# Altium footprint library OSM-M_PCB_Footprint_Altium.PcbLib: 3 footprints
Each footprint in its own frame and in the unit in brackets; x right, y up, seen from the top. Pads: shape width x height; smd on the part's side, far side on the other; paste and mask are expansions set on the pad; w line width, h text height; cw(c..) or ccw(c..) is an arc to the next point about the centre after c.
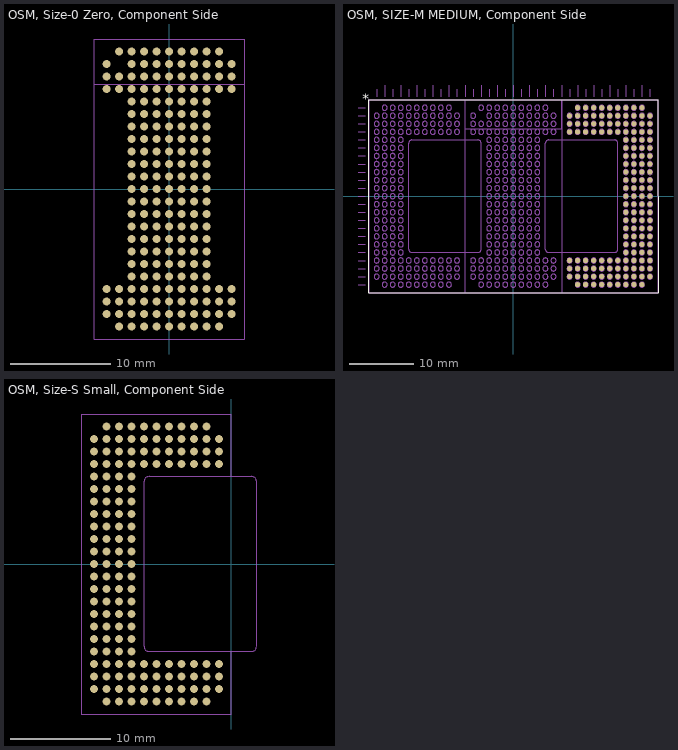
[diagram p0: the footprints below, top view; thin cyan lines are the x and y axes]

## OSM, Size-0 Zero, Component Side [mm] "OSM, Size-0 Zero"
height 3.8
pads (188):
  round 0.8 smd mask+0.051: A14(-5,13.75) A15(-3.75,13.75) A16(-2.5,13.75) A17(-1.25,13.75) A18(0,13.75) A19(1.25,13.75) A20(2.5,13.75) A21(3.75,13.75) A22(5,13.75) AA13(-6.25,-11.25) AA14(-5,-11.25) AA15(-3.75,-11.25) AA16(-2.5,-11.25) AA17(-1.25,-11.25) AA18(0,-11.25) AA19(1.25,-11.25) AA20(2.5,-11.25) AA21(3.75,-11.25) AA22(5,-11.25) AA23(6.25,-11.25) AB13(-6.25,-12.5) AB14(-5,-12.5) AB15(-3.75,-12.5) AB16(-2.5,-12.5) AB17(-1.25,-12.5) AB18(0,-12.5) AB19(1.25,-12.5) AB20(2.5,-12.5) AB21(3.75,-12.5) AB22(5,-12.5) AB23(6.25,-12.5) AC14(-5,-13.75) AC15(-3.75,-13.75) AC16(-2.5,-13.75) AC17(-1.25,-13.75) AC18(0,-13.75) AC19(1.25,-13.75) AC20(2.5,-13.75) AC21(3.75,-13.75) AC22(5,-13.75) B13(-6.25,12.5) B15(-3.75,12.5) B16(-2.5,12.5) B17(-1.25,12.5) B18(0,12.5) B19(1.25,12.5) B20(2.5,12.5) B21(3.75,12.5) B22(5,12.5) B23(6.25,12.5) C13(-6.25,11.25) C14(-5,11.25) C15(-3.75,11.25) C16(-2.5,11.25) C17(-1.25,11.25) C18(0,11.25) C19(1.25,11.25) C20(2.5,11.25) C21(3.75,11.25) C22(5,11.25) C23(6.25,11.25) D13(-6.25,10) D14(-5,10) D15(-3.75,10) D16(-2.5,10) D17(-1.25,10) D18(0,10) D19(1.25,10) D20(2.5,10) D21(3.75,10) D22(5,10) D23(6.25,10) E15(-3.75,8.75) E16(-2.5,8.75) E17(-1.25,8.75) E18(0,8.75) E19(1.25,8.75) E20(2.5,8.75) E21(3.75,8.75) F15(-3.75,7.5) F16(-2.5,7.5) F17(-1.25,7.5) F18(0,7.5) F19(1.25,7.5) F20(2.5,7.5) F21(3.75,7.5) G15(-3.75,6.25) G16(-2.5,6.25) G17(-1.25,6.25) G18(0,6.25) G19(1.25,6.25) G20(2.5,6.25) G21(3.75,6.25) H15(-3.75,5) H16(-2.5,5) H17(-1.25,5) H18(0,5) H19(1.25,5) H20(2.5,5) H21(3.75,5) J15(-3.75,3.75) J16(-2.5,3.75) J17(-1.25,3.75) J18(0,3.75) J19(1.25,3.75) J20(2.5,3.75) J21(3.75,3.75) K15(-3.75,2.5) K16(-2.5,2.5) K17(-1.25,2.5) K18(0,2.5) K19(1.25,2.5) K20(2.5,2.5) K21(3.75,2.5) L15(-3.75,1.25) L16(-2.5,1.25) L17(-1.25,1.25) L18(0,1.25) L19(1.25,1.25) L20(2.5,1.25) L21(3.75,1.25) M15(-3.75,0) M16(-2.5,0) M17(-1.25,0) M18(0,0) M19(1.25,0) M20(2.5,0) M21(3.75,0) N15(-3.75,-1.25) N16(-2.5,-1.25) N17(-1.25,-1.25) N18(0,-1.25) N19(1.25,-1.25) N20(2.5,-1.25) N21(3.75,-1.25) P15(-3.75,-2.5) P16(-2.5,-2.5) P17(-1.25,-2.5) P18(0,-2.5) P19(1.25,-2.5) P20(2.5,-2.5) P21(3.75,-2.5) R15(-3.75,-3.75) R16(-2.5,-3.75) R17(-1.25,-3.75) R18(0,-3.75) R19(1.25,-3.75) R20(2.5,-3.75) R21(3.75,-3.75) T15(-3.75,-5) T16(-2.5,-5) T17(-1.25,-5) T18(0,-5) T19(1.25,-5) T20(2.5,-5) T21(3.75,-5) U15(-3.75,-6.25) U16(-2.5,-6.25) U17(-1.25,-6.25) U18(0,-6.25) U19(1.25,-6.25) U20(2.5,-6.25) U21(3.75,-6.25) V15(-3.75,-7.5) V16(-2.5,-7.5) V17(-1.25,-7.5) V18(0,-7.5) V19(1.25,-7.5) V20(2.5,-7.5) V21(3.75,-7.5) W15(-3.75,-8.75) W16(-2.5,-8.75) W17(-1.25,-8.75) W18(0,-8.75) W19(1.25,-8.75) W20(2.5,-8.75) W21(3.75,-8.75) Y13(-6.25,-10) Y14(-5,-10) Y15(-3.75,-10) Y16(-2.5,-10) Y17(-1.25,-10) Y18(0,-10) Y19(1.25,-10) Y20(2.5,-10) Y21(3.75,-10) Y22(5,-10) Y23(6.25,-10)
Mechanical 13:
  lines w0.025: -7.508,15 -7.5,15 ; -7.5,15 7.5,15 7.5,-15 -7.5,-15 -7.5,15
  lines w0.051: -7.5,15 -7.5,10.5 7.5,10.5
  text "OSM, SIZE-0" at -4.122,12.686 h0.76
  text ".Designator" at -7.747,16.891 h1.52
3D body: height 0.05, standoff 0, extent -5.4,13.35 -4.6,14.15
3D body: height 0.05, standoff 0, extent -4.15,13.35 -3.35,14.15
3D body: height 0.05, standoff 0, extent -2.9,13.35 -2.1,14.15
3D body: height 0.05, standoff 0, extent -1.65,13.35 -0.85,14.15
3D body: height 0.05, standoff 0, extent -0.4,13.35 0.4,14.15
3D body: height 0.05, standoff 0, extent 0.85,13.35 1.65,14.15
3D body: height 0.05, standoff 0, extent 2.1,13.35 2.9,14.15
3D body: height 0.05, standoff 0, extent 3.35,13.35 4.15,14.15
3D body: height 0.05, standoff 0, extent 4.6,13.35 5.4,14.15
3D body: height 0.05, standoff 0, extent -6.65,12.1 -5.85,12.9
3D body: height 0.05, standoff 0, extent -4.15,12.1 -3.35,12.9
3D body: height 0.05, standoff 0, extent -2.9,12.1 -2.1,12.9
3D body: height 0.05, standoff 0, extent -1.65,12.1 -0.85,12.9
3D body: height 0.05, standoff 0, extent -0.4,12.1 0.4,12.9
3D body: height 0.05, standoff 0, extent 0.85,12.1 1.65,12.9
3D body: height 0.05, standoff 0, extent 2.1,12.1 2.9,12.9
3D body: height 0.05, standoff 0, extent 3.35,12.1 4.15,12.9
3D body: height 0.05, standoff 0, extent 4.6,12.1 5.4,12.9
3D body: height 0.05, standoff 0, extent -5.4,10.85 -4.6,11.65
3D body: height 0.05, standoff 0, extent -4.15,10.85 -3.35,11.65
3D body: height 0.05, standoff 0, extent -2.9,10.85 -2.1,11.65
3D body: height 0.05, standoff 0, extent -1.65,10.85 -0.85,11.65
3D body: height 0.05, standoff 0, extent -0.4,10.85 0.4,11.65
3D body: height 0.05, standoff 0, extent 0.85,10.85 1.65,11.65
3D body: height 0.05, standoff 0, extent 2.1,10.85 2.9,11.65
3D body: height 0.05, standoff 0, extent 3.35,10.85 4.15,11.65
3D body: height 0.05, standoff 0, extent 4.6,10.85 5.4,11.65
3D body: height 0.05, standoff 0, extent -5.4,9.6 -4.6,10.4
3D body: height 0.05, standoff 0, extent -4.15,9.6 -3.35,10.4
3D body: height 0.05, standoff 0, extent -2.9,9.6 -2.1,10.4
3D body: height 0.05, standoff 0, extent -1.65,9.6 -0.85,10.4
3D body: height 0.05, standoff 0, extent -0.4,9.6 0.4,10.4
3D body: height 0.05, standoff 0, extent 0.85,9.6 1.65,10.4
3D body: height 0.05, standoff 0, extent 2.1,9.6 2.9,10.4
3D body: height 0.05, standoff 0, extent 3.35,9.6 4.15,10.4
3D body: height 0.05, standoff 0, extent 4.6,9.6 5.4,10.4
3D body: height 0.05, standoff 0, extent -6.65,10.85 -5.85,11.65
3D body: height 0.05, standoff 0, extent -4.15,8.35 -3.35,9.15
3D body: height 0.05, standoff 0, extent -2.9,8.35 -2.1,9.15
3D body: height 0.05, standoff 0, extent -1.65,8.35 -0.85,9.15
3D body: height 0.05, standoff 0, extent -0.4,8.35 0.4,9.15
3D body: height 0.05, standoff 0, extent 0.85,8.35 1.65,9.15
3D body: height 0.05, standoff 0, extent 2.1,8.35 2.9,9.15
3D body: height 0.05, standoff 0, extent 3.35,8.35 4.15,9.15
3D body: height 0.05, standoff 0, extent 5.85,12.1 6.65,12.9
3D body: height 0.05, standoff 0, extent -4.15,7.1 -3.35,7.9
3D body: height 0.05, standoff 0, extent -2.9,7.1 -2.1,7.9
3D body: height 0.05, standoff 0, extent -1.65,7.1 -0.85,7.9
3D body: height 0.05, standoff 0, extent -0.4,7.1 0.4,7.9
3D body: height 0.05, standoff 0, extent 0.85,7.1 1.65,7.9
3D body: height 0.05, standoff 0, extent 2.1,7.1 2.9,7.9
3D body: height 0.05, standoff 0, extent 3.35,7.1 4.15,7.9
3D body: height 0.05, standoff 0, extent -4.15,5.85 -3.35,6.65
3D body: height 0.05, standoff 0, extent -2.9,5.85 -2.1,6.65
3D body: height 0.05, standoff 0, extent -1.65,5.85 -0.85,6.65
3D body: height 0.05, standoff 0, extent -0.4,5.85 0.4,6.65
3D body: height 0.05, standoff 0, extent 0.85,5.85 1.65,6.65
3D body: height 0.05, standoff 0, extent 2.1,5.85 2.9,6.65
3D body: height 0.05, standoff 0, extent 3.35,5.85 4.15,6.65
3D body: height 0.05, standoff 0, extent -4.15,4.6 -3.35,5.4
3D body: height 0.05, standoff 0, extent -2.9,4.6 -2.1,5.4
3D body: height 0.05, standoff 0, extent -1.65,4.6 -0.85,5.4
3D body: height 0.05, standoff 0, extent -0.4,4.6 0.4,5.4
3D body: height 0.05, standoff 0, extent 0.85,4.6 1.65,5.4
3D body: height 0.05, standoff 0, extent 2.1,4.6 2.9,5.4
3D body: height 0.05, standoff 0, extent 3.35,4.6 4.15,5.4
3D body: height 0.05, standoff 0, extent -4.15,3.35 -3.35,4.15
3D body: height 0.05, standoff 0, extent -2.9,3.35 -2.1,4.15
3D body: height 0.05, standoff 0, extent -1.65,3.35 -0.85,4.15
3D body: height 0.05, standoff 0, extent -0.4,3.35 0.4,4.15
3D body: height 0.05, standoff 0, extent 0.85,3.35 1.65,4.15
3D body: height 0.05, standoff 0, extent 2.1,3.35 2.9,4.15
3D body: height 0.05, standoff 0, extent 3.35,3.35 4.15,4.15
3D body: height 0.05, standoff 0, extent -4.15,2.1 -3.35,2.9
3D body: height 0.05, standoff 0, extent -2.9,2.1 -2.1,2.9
3D body: height 0.05, standoff 0, extent -1.65,2.1 -0.85,2.9
3D body: height 0.05, standoff 0, extent -0.4,2.1 0.4,2.9
3D body: height 0.05, standoff 0, extent 0.85,2.1 1.65,2.9
3D body: height 0.05, standoff 0, extent 2.1,2.1 2.9,2.9
3D body: height 0.05, standoff 0, extent 3.35,2.1 4.15,2.9
3D body: height 0.05, standoff 0, extent -4.15,0.85 -3.35,1.65
3D body: height 0.05, standoff 0, extent -2.9,0.85 -2.1,1.65
3D body: height 0.05, standoff 0, extent -1.65,0.85 -0.85,1.65
3D body: height 0.05, standoff 0, extent -0.4,0.85 0.4,1.65
3D body: height 0.05, standoff 0, extent 0.85,0.85 1.65,1.65
3D body: height 0.05, standoff 0, extent 2.1,0.85 2.9,1.65
3D body: height 0.05, standoff 0, extent 3.35,0.85 4.15,1.65
3D body: height 0.05, standoff 0, extent -4.15,-1.65 -3.35,-0.85
3D body: height 0.05, standoff 0, extent -2.9,-1.65 -2.1,-0.85
3D body: height 0.05, standoff 0, extent -1.65,-1.65 -0.85,-0.85
3D body: height 0.05, standoff 0, extent -0.4,-1.65 0.4,-0.85
3D body: height 0.05, standoff 0, extent 0.85,-1.65 1.65,-0.85
3D body: height 0.05, standoff 0, extent 2.1,-1.65 2.9,-0.85
3D body: height 0.05, standoff 0, extent 3.35,-1.65 4.15,-0.85
3D body: height 0.05, standoff 0, extent -4.15,-0.4 -3.35,0.4
3D body: height 0.05, standoff 0, extent -2.9,-0.4 -2.1,0.4
3D body: height 0.05, standoff 0, extent -1.65,-0.4 -0.85,0.4
3D body: height 0.05, standoff 0, extent -0.4,-0.4 0.4,0.4
3D body: height 0.05, standoff 0, extent 0.85,-0.4 1.65,0.4
3D body: height 0.05, standoff 0, extent 2.1,-0.4 2.9,0.4
3D body: height 0.05, standoff 0, extent 3.35,-0.4 4.15,0.4
3D body: height 0.05, standoff 0, extent -4.15,-2.9 -3.35,-2.1
3D body: height 0.05, standoff 0, extent -2.9,-2.9 -2.1,-2.1
3D body: height 0.05, standoff 0, extent -1.65,-2.9 -0.85,-2.1
3D body: height 0.05, standoff 0, extent -0.4,-2.9 0.4,-2.1
3D body: height 0.05, standoff 0, extent 0.85,-2.9 1.65,-2.1
3D body: height 0.05, standoff 0, extent 2.1,-2.9 2.9,-2.1
3D body: height 0.05, standoff 0, extent 3.35,-2.9 4.15,-2.1
3D body: height 0.05, standoff 0, extent -4.15,-4.15 -3.35,-3.35
3D body: height 0.05, standoff 0, extent -2.9,-4.15 -2.1,-3.35
3D body: height 0.05, standoff 0, extent -1.65,-4.15 -0.85,-3.35
3D body: height 0.05, standoff 0, extent -0.4,-4.15 0.4,-3.35
3D body: height 0.05, standoff 0, extent 0.85,-4.15 1.65,-3.35
3D body: height 0.05, standoff 0, extent 2.1,-4.15 2.9,-3.35
3D body: height 0.05, standoff 0, extent 3.35,-4.15 4.15,-3.35
3D body: height 0.05, standoff 0, extent -4.15,-5.4 -3.35,-4.6
3D body: height 0.05, standoff 0, extent -2.9,-5.4 -2.1,-4.6
3D body: height 0.05, standoff 0, extent -1.65,-5.4 -0.85,-4.6
3D body: height 0.05, standoff 0, extent -0.4,-5.4 0.4,-4.6
3D body: height 0.05, standoff 0, extent 0.85,-5.4 1.65,-4.6
3D body: height 0.05, standoff 0, extent 2.1,-5.4 2.9,-4.6
3D body: height 0.05, standoff 0, extent 3.35,-5.4 4.15,-4.6
3D body: height 0.05, standoff 0, extent -4.15,-6.65 -3.35,-5.85
3D body: height 0.05, standoff 0, extent -2.9,-6.65 -2.1,-5.85
3D body: height 0.05, standoff 0, extent -1.65,-6.65 -0.85,-5.85
3D body: height 0.05, standoff 0, extent -0.4,-6.65 0.4,-5.85
3D body: height 0.05, standoff 0, extent 0.85,-6.65 1.65,-5.85
3D body: height 0.05, standoff 0, extent 2.1,-6.65 2.9,-5.85
3D body: height 0.05, standoff 0, extent 3.35,-6.65 4.15,-5.85
3D body: height 0.05, standoff 0, extent -4.15,-7.9 -3.35,-7.1
3D body: height 0.05, standoff 0, extent -2.9,-7.9 -2.1,-7.1
3D body: height 0.05, standoff 0, extent -1.65,-7.9 -0.85,-7.1
3D body: height 0.05, standoff 0, extent -0.4,-7.9 0.4,-7.1
3D body: height 0.05, standoff 0, extent 0.85,-7.9 1.65,-7.1
3D body: height 0.05, standoff 0, extent 2.1,-7.9 2.9,-7.1
3D body: height 0.05, standoff 0, extent 3.35,-7.9 4.15,-7.1
3D body: height 0.05, standoff 0, extent -4.15,-9.15 -3.35,-8.35
3D body: height 0.05, standoff 0, extent -2.9,-9.15 -2.1,-8.35
3D body: height 0.05, standoff 0, extent -1.65,-9.15 -0.85,-8.35
3D body: height 0.05, standoff 0, extent -0.4,-9.15 0.4,-8.35
3D body: height 0.05, standoff 0, extent 0.85,-9.15 1.65,-8.35
3D body: height 0.05, standoff 0, extent 2.1,-9.15 2.9,-8.35
3D body: height 0.05, standoff 0, extent 3.35,-9.15 4.15,-8.35
3D body: height 0.05, standoff 0, extent -4.15,-10.4 -3.35,-9.6
3D body: height 0.05, standoff 0, extent -2.9,-10.4 -2.1,-9.6
3D body: height 0.05, standoff 0, extent -1.65,-10.4 -0.85,-9.6
3D body: height 0.05, standoff 0, extent -0.4,-10.4 0.4,-9.6
3D body: height 0.05, standoff 0, extent 0.85,-10.4 1.65,-9.6
3D body: height 0.05, standoff 0, extent 2.1,-10.4 2.9,-9.6
3D body: height 0.05, standoff 0, extent 3.35,-10.4 4.15,-9.6
3D body: height 0.05, standoff 0, extent -4.15,-11.65 -3.35,-10.85
3D body: height 0.05, standoff 0, extent -2.9,-11.65 -2.1,-10.85
3D body: height 0.05, standoff 0, extent -1.65,-11.65 -0.85,-10.85
3D body: height 0.05, standoff 0, extent -0.4,-11.65 0.4,-10.85
3D body: height 0.05, standoff 0, extent 0.85,-11.65 1.65,-10.85
3D body: height 0.05, standoff 0, extent 2.1,-11.65 2.9,-10.85
3D body: height 0.05, standoff 0, extent 3.35,-11.65 4.15,-10.85
3D body: height 0.05, standoff 0, extent -4.15,-12.9 -3.35,-12.1
3D body: height 0.05, standoff 0, extent -2.9,-12.9 -2.1,-12.1
3D body: height 0.05, standoff 0, extent -1.65,-12.9 -0.85,-12.1
3D body: height 0.05, standoff 0, extent -0.4,-12.9 0.4,-12.1
3D body: height 0.05, standoff 0, extent 0.85,-12.9 1.65,-12.1
3D body: height 0.05, standoff 0, extent 2.1,-12.9 2.9,-12.1
3D body: height 0.05, standoff 0, extent 3.35,-12.9 4.15,-12.1
3D body: height 0.05, standoff 0, extent -4.15,-14.15 -3.35,-13.35
3D body: height 0.05, standoff 0, extent -2.9,-14.15 -2.1,-13.35
3D body: height 0.05, standoff 0, extent -1.65,-14.15 -0.85,-13.35
3D body: height 0.05, standoff 0, extent -0.4,-14.15 0.4,-13.35
3D body: height 0.05, standoff 0, extent 0.85,-14.15 1.65,-13.35
3D body: height 0.05, standoff 0, extent 2.1,-14.15 2.9,-13.35
3D body: height 0.05, standoff 0, extent 3.35,-14.15 4.15,-13.35
3D body: height 0.05, standoff 0, extent 5.85,10.85 6.65,11.65
3D body: height 0.05, standoff 0, extent 5.85,9.6 6.65,10.4
3D body: height 0.05, standoff 0, extent -6.65,9.6 -5.85,10.4
3D body: height 0.05, standoff 0, extent -5.4,-10.4 -4.6,-9.6
3D body: height 0.05, standoff 0, extent -5.4,-11.65 -4.6,-10.85
3D body: height 0.05, standoff 0, extent -5.4,-12.9 -4.6,-12.1
3D body: height 0.05, standoff 0, extent -5.4,-14.15 -4.6,-13.35
3D body: height 0.05, standoff 0, extent -6.65,-10.4 -5.85,-9.6
3D body: height 0.05, standoff 0, extent -6.65,-11.65 -5.85,-10.85
3D body: height 0.05, standoff 0, extent -6.65,-12.9 -5.85,-12.1
3D body: height 0.05, standoff 0, extent 4.6,-14.15 5.4,-13.35
3D body: height 0.05, standoff 0, extent 4.6,-10.4 5.4,-9.6
3D body: height 0.05, standoff 0, extent 4.6,-11.65 5.4,-10.85
3D body: height 0.05, standoff 0, extent 4.6,-12.9 5.4,-12.1
3D body: height 0.05, standoff 0, extent 5.85,-10.4 6.65,-9.6
3D body: height 0.05, standoff 0, extent 5.85,-11.65 6.65,-10.85
3D body: height 0.05, standoff 0, extent 5.85,-12.9 6.65,-12.1

## OSM, SIZE-M MEDIUM, Component Side [mm] "OSM, Size-M Medium"
height 3.8
pads (144):
  round 0.8 smd mask+0.051: A26(10,13.75) A27(11.25,13.75) A28(12.5,13.75) A29(13.75,13.75) A30(15,13.75) A31(16.25,13.75) A32(17.5,13.75) A33(18.75,13.75) A34(20,13.75) AA25(8.75,-11.25) AA26(10,-11.25) AA27(11.25,-11.25) AA28(12.5,-11.25) AA29(13.75,-11.25) AA30(15,-11.25) AA31(16.25,-11.25) AA32(17.5,-11.25) AA33(18.75,-11.25) AA34(20,-11.25) AA35(21.25,-11.25) AB25(8.75,-12.5) AB26(10,-12.5) AB27(11.25,-12.5) AB28(12.5,-12.5) AB29(13.75,-12.5) AB30(15,-12.5) AB31(16.25,-12.5) AB32(17.5,-12.5) AB33(18.75,-12.5) AB34(20,-12.5) AB35(21.25,-12.5) AC26(10,-13.75) AC27(11.25,-13.75) AC28(12.5,-13.75) AC29(13.75,-13.75) AC30(15,-13.75) AC31(16.25,-13.75) AC32(17.5,-13.75) AC33(18.75,-13.75) AC34(20,-13.75) B25(8.75,12.5) B26(10,12.5) B27(11.25,12.5) B28(12.5,12.5) B29(13.75,12.5) B30(15,12.5) B31(16.25,12.5) B32(17.5,12.5) B33(18.75,12.5) B34(20,12.5) B35(21.25,12.5) C25(8.75,11.25) C26(10,11.25) C27(11.25,11.25) C28(12.5,11.25) C29(13.75,11.25) C30(15,11.25) C31(16.25,11.25) C32(17.5,11.25) C33(18.75,11.25) C34(20,11.25) C35(21.25,11.25) D25(8.75,10) D26(10,10) D27(11.25,10) D28(12.5,10) D29(13.75,10) D30(15,10) D31(16.25,10) D32(17.5,10) D33(18.75,10) D34(20,10) D35(21.25,10) E32(17.5,8.75) E33(18.75,8.75) E34(20,8.75) E35(21.25,8.75) F32(17.5,7.5) F33(18.75,7.5) F34(20,7.5) F35(21.25,7.5) G32(17.5,6.25) G33(18.75,6.25) G34(20,6.25) G35(21.25,6.25) H32(17.5,5) H33(18.75,5) H34(20,5) H35(21.25,5) J32(17.5,3.75) J33(18.75,3.75) J34(20,3.75) J35(21.25,3.75) K32(17.5,2.5) K33(18.75,2.5) K34(20,2.5) K35(21.25,2.5) L32(17.5,1.25) L33(18.75,1.25) L34(20,1.25) L35(21.25,1.25) M32(17.5,0) M33(18.75,0) M34(20,0) M35(21.25,0) N32(17.5,-1.25) N33(18.75,-1.25) N34(20,-1.25) N35(21.25,-1.25) P32(17.5,-2.5) P33(18.75,-2.5) P34(20,-2.5) P35(21.25,-2.5) R32(17.5,-3.75) R33(18.75,-3.75) R34(20,-3.75) R35(21.25,-3.75) T32(17.5,-5) T33(18.75,-5) T34(20,-5) T35(21.25,-5) U32(17.5,-6.25) U33(18.75,-6.25) U34(20,-6.25) U35(21.25,-6.25) V32(17.5,-7.5) V33(18.75,-7.5) V34(20,-7.5) V35(21.25,-7.5) W32(17.5,-8.75) W33(18.75,-8.75) W34(20,-8.75) W35(21.25,-8.75) Y25(8.75,-10) Y26(10,-10) Y27(11.25,-10) Y28(12.5,-10) Y29(13.75,-10) Y30(15,-10) Y31(16.25,-10) Y32(17.5,-10) Y33(18.75,-10) Y34(20,-10) Y35(21.25,-10)
Top Overlay:
  lines w0.102: -22.5,-15 22.5,-15 22.5,15 -22.5,15 -22.5,-15
  text "*" at -22.417,14.398 h1.52
Mechanical 7:
  drawing of 1973 lines, arcs and shapes, not listed
  text "35" at 20.853,16.879 h0.64
  text "34" at 19.603,17.471 h0.64
  text "33" at 18.353,16.879 h0.64
  text "AC" at -25.678,-14.035 h0.76
  text "A" at -24.887,13.465 h0.76
  text "AB" at -25.677,-12.785 h0.76
  text "AA" at -25.677,-11.535 h0.76
  text "Y" at -24.887,-10.285 h0.76
  text "W" at -24.887,-9.035 h0.76
  text "V" at -24.887,-7.785 h0.76
  text "U" at -24.887,-6.535 h0.76
  text "T" at -24.887,-5.285 h0.76
  text "R" at -24.887,-4.035 h0.76
  text "P" at -24.887,-2.785 h0.76
  text "N" at -24.887,-1.535 h0.76
  text "M" at -24.887,-0.285 h0.76
  text "L" at -24.887,0.965 h0.76
  text "K" at -24.887,2.215 h0.76
  text "J" at -24.887,3.465 h0.76
  text "H" at -24.887,4.715 h0.76
  text "G" at -24.887,5.965 h0.76
  text "F" at -24.887,7.215 h0.76
  text "E" at -24.887,8.465 h0.76
  text "D" at -24.887,9.715 h0.76
  text "C" at -24.887,10.965 h0.76
  text "B" at -24.887,12.215 h0.76
  text "2" at -20.258,17.471 h0.64
  text "1" at -21.509,16.879 h0.64
  text "4" at -17.758,17.471 h0.64
  text "3" at -19.009,16.879 h0.64
  text "6" at -15.258,17.471 h0.64
  text "5" at -16.509,16.879 h0.64
  text "8" at -12.759,17.471 h0.64
  text "7" at -14.009,16.879 h0.64
  text "10" at -10.397,17.471 h0.64
  text "9" at -11.509,16.879 h0.64
  text "12" at -7.897,17.471 h0.64
  text "11" at -9.147,16.879 h0.64
  text "14" at -5.397,17.471 h0.64
  text "13" at -6.647,16.879 h0.64
  text "16" at -2.897,17.471 h0.64
  text "15" at -4.148,16.879 h0.64
  text "18" at -0.397,17.471 h0.64
  text "17" at -1.648,16.879 h0.64
  text "20" at 2.103,17.471 h0.64
  text "19" at 0.853,16.879 h0.64
  text "22" at 4.603,17.471 h0.64
  text "21" at 3.352,16.879 h0.64
  text "24" at 7.103,17.471 h0.64
  text "23" at 5.853,16.879 h0.64
  text "25" at 8.353,16.879 h0.64
  text "26" at 9.603,17.471 h0.64
  text "27" at 10.853,16.879 h0.64
  text "28" at 12.103,17.471 h0.64
  text "29" at 13.352,16.879 h0.64
  text "30" at 14.603,17.471 h0.64
  text "31" at 15.853,16.879 h0.64
  text "32" at 17.103,17.471 h0.64
Mechanical 13:
  lines w0.025: 7.5,10.5 7.5,15 ; -22.5,-15 22.5,-15 22.5,15 -22.5,15 -22.5,-15
  lines w0.051: -7.5,15 -7.5,10.5 7.5,10.5 ; -16.25,-8.25 ccw(c-15.75,-8.25) -15.75,-8.75 -5.5,-8.75 ccw(c-5.5,-8.25) -5,-8.25 -5,8.25 ccw(c-5.5,8.25) -5.5,8.75 -15.75,8.75 ccw(c-15.75,8.25) -16.25,8.25 -16.25,-8.25 ; 5,-8.25 ccw(c5.5,-8.25) 5.5,-8.75 15.75,-8.75 ccw(c15.75,-8.25) 16.25,-8.25 16.25,8.25 ccw(c15.75,8.25) 15.75,8.75 5.5,8.75 ccw(c5.5,8.25) 5,8.25 5,-8.25
  text "*" at -20.904,12.613 h1.52
  text "OSM, SIZE-S" at -14.732,-1.778 h0.76
  text "OSM, SIZE-M" at 6.604,-1.651 h0.76
  text "OSM, SIZE-0" at -3.905,12.062 h0.76
3D body: height 0.05, standoff 0, extent 9.6,13.35 10.4,14.15
3D body: height 0.05, standoff 0, extent 10.85,13.35 11.65,14.15
3D body: height 0.05, standoff 0, extent 12.1,13.35 12.9,14.15
3D body: height 0.05, standoff 0, extent 13.35,13.35 14.15,14.15
3D body: height 0.05, standoff 0, extent 14.6,13.35 15.4,14.15
3D body: height 0.05, standoff 0, extent 15.85,13.35 16.65,14.15
3D body: height 0.05, standoff 0, extent 17.1,13.35 17.9,14.15
3D body: height 0.05, standoff 0, extent 9.6,12.1 10.4,12.9
3D body: height 0.05, standoff 0, extent 10.85,12.1 11.65,12.9
3D body: height 0.05, standoff 0, extent 12.1,12.1 12.9,12.9
3D body: height 0.05, standoff 0, extent 13.35,12.1 14.15,12.9
3D body: height 0.05, standoff 0, extent 14.6,12.1 15.4,12.9
3D body: height 0.05, standoff 0, extent 15.85,12.1 16.65,12.9
3D body: height 0.05, standoff 0, extent 17.1,12.1 17.9,12.9
3D body: height 0.05, standoff 0, extent 9.6,10.85 10.4,11.65
3D body: height 0.05, standoff 0, extent 10.85,10.85 11.65,11.65
3D body: height 0.05, standoff 0, extent 12.1,10.85 12.9,11.65
3D body: height 0.05, standoff 0, extent 13.35,10.85 14.15,11.65
3D body: height 0.05, standoff 0, extent 14.6,10.85 15.4,11.65
3D body: height 0.05, standoff 0, extent 15.85,10.85 16.65,11.65
3D body: height 0.05, standoff 0, extent 17.1,10.85 17.9,11.65
3D body: height 0.05, standoff 0, extent 9.6,9.6 10.4,10.4
3D body: height 0.05, standoff 0, extent 10.85,9.6 11.65,10.4
3D body: height 0.05, standoff 0, extent 12.1,9.6 12.9,10.4
3D body: height 0.05, standoff 0, extent 13.35,9.6 14.15,10.4
3D body: height 0.05, standoff 0, extent 14.6,9.6 15.4,10.4
3D body: height 0.05, standoff 0, extent 15.85,9.6 16.65,10.4
3D body: height 0.05, standoff 0, extent 17.1,9.6 17.9,10.4
3D body: height 0.05, standoff 0, extent 8.35,9.6 9.15,10.4
3D body: height 0.05, standoff 0, extent 8.35,10.85 9.15,11.65
3D body: height 0.05, standoff 0, extent 8.35,12.1 9.15,12.9
3D body: height 0.05, standoff 0, extent 19.6,13.35 20.4,14.15
3D body: height 0.05, standoff 0, extent 18.35,13.35 19.15,14.15
3D body: height 0.05, standoff 0, extent 17.1,8.35 17.9,9.15
3D body: height 0.05, standoff 0, extent 18.35,-5.4 19.15,-4.6
3D body: height 0.05, standoff 0, extent 19.6,-5.4 20.4,-4.6
3D body: height 0.05, standoff 0, extent 19.6,12.1 20.4,12.9
3D body: height 0.05, standoff 0, extent 20.85,12.1 21.65,12.9
3D body: height 0.05, standoff 0, extent 18.35,12.1 19.15,12.9
3D body: height 0.05, standoff 0, extent 17.1,7.1 17.9,7.9
3D body: height 0.05, standoff 0, extent 18.35,-6.65 19.15,-5.85
3D body: height 0.05, standoff 0, extent 19.6,-6.65 20.4,-5.85
3D body: height 0.05, standoff 0, extent 19.6,10.85 20.4,11.65
3D body: height 0.05, standoff 0, extent 20.85,10.85 21.65,11.65
3D body: height 0.05, standoff 0, extent 18.35,10.85 19.15,11.65
3D body: height 0.05, standoff 0, extent 17.1,5.85 17.9,6.65
3D body: height 0.05, standoff 0, extent 18.35,-7.9 19.15,-7.1
3D body: height 0.05, standoff 0, extent 19.6,-7.9 20.4,-7.1
3D body: height 0.05, standoff 0, extent 19.6,9.6 20.4,10.4
3D body: height 0.05, standoff 0, extent 20.85,9.6 21.65,10.4
3D body: height 0.05, standoff 0, extent 18.35,9.6 19.15,10.4
3D body: height 0.05, standoff 0, extent 17.1,4.6 17.9,5.4
3D body: height 0.05, standoff 0, extent 18.35,-9.15 19.15,-8.35
3D body: height 0.05, standoff 0, extent 19.6,-9.15 20.4,-8.35
3D body: height 0.05, standoff 0, extent 19.6,8.35 20.4,9.15
3D body: height 0.05, standoff 0, extent 20.85,8.35 21.65,9.15
3D body: height 0.05, standoff 0, extent 18.35,8.35 19.15,9.15
3D body: height 0.05, standoff 0, extent 17.1,3.35 17.9,4.15
3D body: height 0.05, standoff 0, extent 18.35,-10.4 19.15,-9.6
3D body: height 0.05, standoff 0, extent 19.6,-10.4 20.4,-9.6
3D body: height 0.05, standoff 0, extent 19.6,7.1 20.4,7.9
3D body: height 0.05, standoff 0, extent 20.85,7.1 21.65,7.9
3D body: height 0.05, standoff 0, extent 18.35,7.1 19.15,7.9
3D body: height 0.05, standoff 0, extent 17.1,2.1 17.9,2.9
3D body: height 0.05, standoff 0, extent 18.35,-11.65 19.15,-10.85
3D body: height 0.05, standoff 0, extent 19.6,-11.65 20.4,-10.85
3D body: height 0.05, standoff 0, extent 19.6,5.85 20.4,6.65
3D body: height 0.05, standoff 0, extent 20.85,5.85 21.65,6.65
3D body: height 0.05, standoff 0, extent 18.35,5.85 19.15,6.65
3D body: height 0.05, standoff 0, extent 17.1,0.85 17.9,1.65
3D body: height 0.05, standoff 0, extent 18.35,-14.15 19.15,-13.35
3D body: height 0.05, standoff 0, extent 19.6,-14.15 20.4,-13.35
3D body: height 0.05, standoff 0, extent 19.6,3.35 20.4,4.15
3D body: height 0.05, standoff 0, extent 20.85,3.35 21.65,4.15
3D body: height 0.05, standoff 0, extent 18.35,3.35 19.15,4.15
3D body: height 0.05, standoff 0, extent 17.1,-1.65 17.9,-0.85
3D body: height 0.05, standoff 0, extent 18.35,-12.9 19.15,-12.1
3D body: height 0.05, standoff 0, extent 19.6,-12.9 20.4,-12.1
3D body: height 0.05, standoff 0, extent 19.6,4.6 20.4,5.4
3D body: height 0.05, standoff 0, extent 20.85,4.6 21.65,5.4
3D body: height 0.05, standoff 0, extent 18.35,4.6 19.15,5.4
3D body: height 0.05, standoff 0, extent 17.1,-0.4 17.9,0.4
3D body: height 0.05, standoff 0, extent 20.85,-5.4 21.65,-4.6
3D body: height 0.05, standoff 0, extent 20.85,-12.9 21.65,-12.1
3D body: height 0.05, standoff 0, extent 19.6,2.1 20.4,2.9
3D body: height 0.05, standoff 0, extent 20.85,2.1 21.65,2.9
3D body: height 0.05, standoff 0, extent 18.35,2.1 19.15,2.9
3D body: height 0.05, standoff 0, extent 17.1,-2.9 17.9,-2.1
3D body: height 0.05, standoff 0, extent 20.85,-6.65 21.65,-5.85
3D body: height 0.05, standoff 0, extent 19.6,0.85 20.4,1.65
3D body: height 0.05, standoff 0, extent 20.85,0.85 21.65,1.65
3D body: height 0.05, standoff 0, extent 18.35,0.85 19.15,1.65
3D body: height 0.05, standoff 0, extent 17.1,-4.15 17.9,-3.35
3D body: height 0.05, standoff 0, extent 20.85,-7.9 21.65,-7.1
3D body: height 0.05, standoff 0, extent 19.6,-0.4 20.4,0.4
3D body: height 0.05, standoff 0, extent 20.85,-0.4 21.65,0.4
3D body: height 0.05, standoff 0, extent 18.35,-0.4 19.15,0.4
3D body: height 0.05, standoff 0, extent 17.1,-5.4 17.9,-4.6
3D body: height 0.05, standoff 0, extent 8.35,-10.4 9.15,-9.6
3D body: height 0.05, standoff 0, extent 20.85,-9.15 21.65,-8.35
3D body: height 0.05, standoff 0, extent 19.6,-1.65 20.4,-0.85
3D body: height 0.05, standoff 0, extent 20.85,-1.65 21.65,-0.85
3D body: height 0.05, standoff 0, extent 18.35,-1.65 19.15,-0.85
3D body: height 0.05, standoff 0, extent 17.1,-6.65 17.9,-5.85
3D body: height 0.05, standoff 0, extent 8.35,-11.65 9.15,-10.85
3D body: height 0.05, standoff 0, extent 20.85,-10.4 21.65,-9.6
3D body: height 0.05, standoff 0, extent 19.6,-2.9 20.4,-2.1
3D body: height 0.05, standoff 0, extent 20.85,-2.9 21.65,-2.1
3D body: height 0.05, standoff 0, extent 18.35,-2.9 19.15,-2.1
3D body: height 0.05, standoff 0, extent 17.1,-7.9 17.9,-7.1
3D body: height 0.05, standoff 0, extent 8.35,-12.9 9.15,-12.1
3D body: height 0.05, standoff 0, extent 20.85,-11.65 21.65,-10.85
3D body: height 0.05, standoff 0, extent 19.6,-4.15 20.4,-3.35
3D body: height 0.05, standoff 0, extent 20.85,-4.15 21.65,-3.35
3D body: height 0.05, standoff 0, extent 18.35,-4.15 19.15,-3.35
3D body: height 0.05, standoff 0, extent 17.1,-9.15 17.9,-8.35
3D body: height 0.05, standoff 0, extent 9.6,-10.4 10.4,-9.6
3D body: height 0.05, standoff 0, extent 10.85,-10.4 11.65,-9.6
3D body: height 0.05, standoff 0, extent 12.1,-10.4 12.9,-9.6
3D body: height 0.05, standoff 0, extent 13.35,-10.4 14.15,-9.6
3D body: height 0.05, standoff 0, extent 14.6,-10.4 15.4,-9.6
3D body: height 0.05, standoff 0, extent 15.85,-10.4 16.65,-9.6
3D body: height 0.05, standoff 0, extent 17.1,-10.4 17.9,-9.6
3D body: height 0.05, standoff 0, extent 9.6,-11.65 10.4,-10.85
3D body: height 0.05, standoff 0, extent 10.85,-11.65 11.65,-10.85
3D body: height 0.05, standoff 0, extent 12.1,-11.65 12.9,-10.85
3D body: height 0.05, standoff 0, extent 13.35,-11.65 14.15,-10.85
3D body: height 0.05, standoff 0, extent 14.6,-11.65 15.4,-10.85
3D body: height 0.05, standoff 0, extent 15.85,-11.65 16.65,-10.85
3D body: height 0.05, standoff 0, extent 17.1,-11.65 17.9,-10.85
3D body: height 0.05, standoff 0, extent 9.6,-12.9 10.4,-12.1
3D body: height 0.05, standoff 0, extent 10.85,-12.9 11.65,-12.1
3D body: height 0.05, standoff 0, extent 12.1,-12.9 12.9,-12.1
3D body: height 0.05, standoff 0, extent 13.35,-12.9 14.15,-12.1
3D body: height 0.05, standoff 0, extent 14.6,-12.9 15.4,-12.1
3D body: height 0.05, standoff 0, extent 15.85,-12.9 16.65,-12.1
3D body: height 0.05, standoff 0, extent 17.1,-12.9 17.9,-12.1
3D body: height 0.05, standoff 0, extent 9.6,-14.15 10.4,-13.35
3D body: height 0.05, standoff 0, extent 10.85,-14.15 11.65,-13.35
3D body: height 0.05, standoff 0, extent 12.1,-14.15 12.9,-13.35
3D body: height 0.05, standoff 0, extent 13.35,-14.15 14.15,-13.35
3D body: height 0.05, standoff 0, extent 14.6,-14.15 15.4,-13.35
3D body: height 0.05, standoff 0, extent 15.85,-14.15 16.65,-13.35
3D body: height 0.05, standoff 0, extent 17.1,-14.15 17.9,-13.35

## OSM, Size-S Small, Component Side [mm] "OSM, Size-S Small"
height 3.8
pads (144):
  round 0.8 smd mask+0.051: A2(-12.5,13.75) A3(-11.25,13.75) A4(-10,13.75) A5(-8.75,13.75) A6(-7.5,13.75) A7(-6.25,13.75) A8(-5,13.75) A9(-3.75,13.75) A10(-2.5,13.75) AA1(-13.75,-11.25) AA2(-12.5,-11.25) AA3(-11.25,-11.25) AA4(-10,-11.25) AA5(-8.75,-11.25) AA6(-7.5,-11.25) AA7(-6.25,-11.25) AA8(-5,-11.25) AA9(-3.75,-11.25) AA10(-2.5,-11.25) AA11(-1.25,-11.25) AB1(-13.75,-12.5) AB2(-12.5,-12.5) AB3(-11.25,-12.5) AB4(-10,-12.5) AB5(-8.75,-12.5) AB6(-7.5,-12.5) AB7(-6.25,-12.5) AB8(-5,-12.5) AB9(-3.75,-12.5) AB10(-2.5,-12.5) AB11(-1.25,-12.5) AC2(-12.5,-13.75) AC3(-11.25,-13.75) AC4(-10,-13.75) AC5(-8.75,-13.75) AC6(-7.5,-13.75) AC7(-6.25,-13.75) AC8(-5,-13.75) AC9(-3.75,-13.75) AC10(-2.5,-13.75) B1(-13.75,12.5) B2(-12.5,12.5) B3(-11.25,12.5) B4(-10,12.5) B5(-8.75,12.5) B6(-7.5,12.5) B7(-6.25,12.5) B8(-5,12.5) B9(-3.75,12.5) B10(-2.5,12.5) B11(-1.25,12.5) C1(-13.75,11.25) C2(-12.5,11.25) C3(-11.25,11.25) C4(-10,11.25) C5(-8.75,11.25) C6(-7.5,11.25) C7(-6.25,11.25) C8(-5,11.25) C9(-3.75,11.25) C10(-2.5,11.25) C11(-1.25,11.25) D1(-13.75,10) D2(-12.5,10) D3(-11.25,10) D4(-10,10) D5(-8.75,10) D6(-7.5,10) D7(-6.25,10) D8(-5,10) D9(-3.75,10) D10(-2.5,10) D11(-1.25,10) E1(-13.75,8.75) E2(-12.5,8.75) E3(-11.25,8.75) E4(-10,8.75) F1(-13.75,7.5) F2(-12.5,7.5) F3(-11.25,7.5) F4(-10,7.5) G1(-13.75,6.25) G2(-12.5,6.25) G3(-11.25,6.25) G4(-10,6.25) H1(-13.75,5) H2(-12.5,5) H3(-11.25,5) H4(-10,5) J1(-13.75,3.75) J2(-12.5,3.75) J3(-11.25,3.75) J4(-10,3.75) K1(-13.75,2.5) K2(-12.5,2.5) K3(-11.25,2.5) K4(-10,2.5) L1(-13.75,1.25) L2(-12.5,1.25) L3(-11.25,1.25) L4(-10,1.25) M1(-13.75,0) M2(-12.5,0) M3(-11.25,0) M4(-10,0) N1(-13.75,-1.25) N2(-12.5,-1.25) N3(-11.25,-1.25) N4(-10,-1.25) P1(-13.75,-2.5) P2(-12.5,-2.5) P3(-11.25,-2.5) P4(-10,-2.5) R1(-13.75,-3.75) R2(-12.5,-3.75) R3(-11.25,-3.75) R4(-10,-3.75) T1(-13.75,-5) T2(-12.5,-5) T3(-11.25,-5) T4(-10,-5) U1(-13.75,-6.25) U2(-12.5,-6.25) U3(-11.25,-6.25) U4(-10,-6.25) V1(-13.75,-7.5) V2(-12.5,-7.5) V3(-11.25,-7.5) V4(-10,-7.5) W1(-13.75,-8.75) W2(-12.5,-8.75) W3(-11.25,-8.75) W4(-10,-8.75) Y1(-13.75,-10) Y2(-12.5,-10) Y3(-11.25,-10) Y4(-10,-10) Y5(-8.75,-10) Y6(-7.5,-10) Y7(-6.25,-10) Y8(-5,-10) Y9(-3.75,-10) Y10(-2.5,-10) Y11(-1.25,-10)
Mechanical 13:
  lines w0.025: 0,-8.763 0,-15 -15,-15 -15,15 0,15 0,8.763
  lines w0.051: -8.75,-8.25 ccw(c-8.25,-8.25) -8.25,-8.75 2,-8.75 ccw(c2,-8.25) 2.5,-8.25 2.5,8.25 ccw(c2,8.25) 2,8.75 -8.25,8.75 ccw(c-8.25,8.25) -8.75,8.25 -8.75,-8.25
  text "*" at -13.404,12.613 h1.52
  text "OSM, SIZE-S" at -6.785,-0.802 h0.76
3D body: height 0.05, standoff 0, extent -10.4,-14.15 -9.6,-13.35
3D body: height 0.05, standoff 0, extent -9.15,-14.15 -8.35,-13.35
3D body: height 0.05, standoff 0, extent -7.9,-14.15 -7.1,-13.35
3D body: height 0.05, standoff 0, extent -6.65,-14.15 -5.85,-13.35
3D body: height 0.05, standoff 0, extent -5.4,-14.15 -4.6,-13.35
3D body: height 0.05, standoff 0, extent -4.15,-14.15 -3.35,-13.35
3D body: height 0.05, standoff 0, extent -2.9,-14.15 -2.1,-13.35
3D body: height 0.05, standoff 0, extent -10.4,-12.9 -9.6,-12.1
3D body: height 0.05, standoff 0, extent -9.15,-12.9 -8.35,-12.1
3D body: height 0.05, standoff 0, extent -7.9,-12.9 -7.1,-12.1
3D body: height 0.05, standoff 0, extent -6.65,-12.9 -5.85,-12.1
3D body: height 0.05, standoff 0, extent -5.4,-12.9 -4.6,-12.1
3D body: height 0.05, standoff 0, extent -4.15,-12.9 -3.35,-12.1
3D body: height 0.05, standoff 0, extent -2.9,-12.9 -2.1,-12.1
3D body: height 0.05, standoff 0, extent -10.4,-11.65 -9.6,-10.85
3D body: height 0.05, standoff 0, extent -9.15,-11.65 -8.35,-10.85
3D body: height 0.05, standoff 0, extent -7.9,-11.65 -7.1,-10.85
3D body: height 0.05, standoff 0, extent -6.65,-11.65 -5.85,-10.85
3D body: height 0.05, standoff 0, extent -5.4,-11.65 -4.6,-10.85
3D body: height 0.05, standoff 0, extent -4.15,-11.65 -3.35,-10.85
3D body: height 0.05, standoff 0, extent -2.9,-11.65 -2.1,-10.85
3D body: height 0.05, standoff 0, extent -10.4,-10.4 -9.6,-9.6
3D body: height 0.05, standoff 0, extent -9.15,-10.4 -8.35,-9.6
3D body: height 0.05, standoff 0, extent -7.9,-10.4 -7.1,-9.6
3D body: height 0.05, standoff 0, extent -6.65,-10.4 -5.85,-9.6
3D body: height 0.05, standoff 0, extent -5.4,-10.4 -4.6,-9.6
3D body: height 0.05, standoff 0, extent -4.15,-10.4 -3.35,-9.6
3D body: height 0.05, standoff 0, extent -2.9,-10.4 -2.1,-9.6
3D body: height 0.05, standoff 0, extent -10.4,-9.15 -9.6,-8.35
3D body: height 0.05, standoff 0, extent -11.65,-4.15 -10.85,-3.35
3D body: height 0.05, standoff 0, extent -14.15,-4.15 -13.35,-3.35
3D body: height 0.05, standoff 0, extent -12.9,-4.15 -12.1,-3.35
3D body: height 0.05, standoff 0, extent -14.15,-11.65 -13.35,-10.85
3D body: height 0.05, standoff 0, extent -1.65,-12.9 -0.85,-12.1
3D body: height 0.05, standoff 0, extent -10.4,-7.9 -9.6,-7.1
3D body: height 0.05, standoff 0, extent -11.65,-2.9 -10.85,-2.1
3D body: height 0.05, standoff 0, extent -14.15,-2.9 -13.35,-2.1
3D body: height 0.05, standoff 0, extent -12.9,-2.9 -12.1,-2.1
3D body: height 0.05, standoff 0, extent -14.15,-10.4 -13.35,-9.6
3D body: height 0.05, standoff 0, extent -1.65,-11.65 -0.85,-10.85
3D body: height 0.05, standoff 0, extent -10.4,-6.65 -9.6,-5.85
3D body: height 0.05, standoff 0, extent -11.65,-1.65 -10.85,-0.85
3D body: height 0.05, standoff 0, extent -14.15,-1.65 -13.35,-0.85
3D body: height 0.05, standoff 0, extent -12.9,-1.65 -12.1,-0.85
3D body: height 0.05, standoff 0, extent -14.15,-9.15 -13.35,-8.35
3D body: height 0.05, standoff 0, extent -1.65,-10.4 -0.85,-9.6
3D body: height 0.05, standoff 0, extent -10.4,-5.4 -9.6,-4.6
3D body: height 0.05, standoff 0, extent -11.65,-0.4 -10.85,0.4
3D body: height 0.05, standoff 0, extent -14.15,-0.4 -13.35,0.4
3D body: height 0.05, standoff 0, extent -12.9,-0.4 -12.1,0.4
3D body: height 0.05, standoff 0, extent -14.15,-7.9 -13.35,-7.1
3D body: height 0.05, standoff 0, extent -10.4,-4.15 -9.6,-3.35
3D body: height 0.05, standoff 0, extent -11.65,0.85 -10.85,1.65
3D body: height 0.05, standoff 0, extent -14.15,0.85 -13.35,1.65
3D body: height 0.05, standoff 0, extent -12.9,0.85 -12.1,1.65
3D body: height 0.05, standoff 0, extent -14.15,-6.65 -13.35,-5.85
3D body: height 0.05, standoff 0, extent -10.4,-2.9 -9.6,-2.1
3D body: height 0.05, standoff 0, extent -11.65,2.1 -10.85,2.9
3D body: height 0.05, standoff 0, extent -14.15,2.1 -13.35,2.9
3D body: height 0.05, standoff 0, extent -12.9,2.1 -12.1,2.9
3D body: height 0.05, standoff 0, extent -14.15,-12.9 -13.35,-12.1
3D body: height 0.05, standoff 0, extent -14.15,-5.4 -13.35,-4.6
3D body: height 0.05, standoff 0, extent -10.4,-0.4 -9.6,0.4
3D body: height 0.05, standoff 0, extent -11.65,4.6 -10.85,5.4
3D body: height 0.05, standoff 0, extent -14.15,4.6 -13.35,5.4
3D body: height 0.05, standoff 0, extent -12.9,4.6 -12.1,5.4
3D body: height 0.05, standoff 0, extent -12.9,-12.9 -12.1,-12.1
3D body: height 0.05, standoff 0, extent -11.65,-12.9 -10.85,-12.1
3D body: height 0.05, standoff 0, extent -10.4,-1.65 -9.6,-0.85
3D body: height 0.05, standoff 0, extent -11.65,3.35 -10.85,4.15
3D body: height 0.05, standoff 0, extent -14.15,3.35 -13.35,4.15
3D body: height 0.05, standoff 0, extent -12.9,3.35 -12.1,4.15
3D body: height 0.05, standoff 0, extent -12.9,-14.15 -12.1,-13.35
3D body: height 0.05, standoff 0, extent -11.65,-14.15 -10.85,-13.35
3D body: height 0.05, standoff 0, extent -10.4,0.85 -9.6,1.65
3D body: height 0.05, standoff 0, extent -11.65,5.85 -10.85,6.65
3D body: height 0.05, standoff 0, extent -14.15,5.85 -13.35,6.65
3D body: height 0.05, standoff 0, extent -12.9,5.85 -12.1,6.65
3D body: height 0.05, standoff 0, extent -12.9,-11.65 -12.1,-10.85
3D body: height 0.05, standoff 0, extent -11.65,-11.65 -10.85,-10.85
3D body: height 0.05, standoff 0, extent -10.4,2.1 -9.6,2.9
3D body: height 0.05, standoff 0, extent -11.65,7.1 -10.85,7.9
3D body: height 0.05, standoff 0, extent -14.15,7.1 -13.35,7.9
3D body: height 0.05, standoff 0, extent -12.9,7.1 -12.1,7.9
3D body: height 0.05, standoff 0, extent -12.9,-10.4 -12.1,-9.6
3D body: height 0.05, standoff 0, extent -11.65,-10.4 -10.85,-9.6
3D body: height 0.05, standoff 0, extent -10.4,3.35 -9.6,4.15
3D body: height 0.05, standoff 0, extent -11.65,8.35 -10.85,9.15
3D body: height 0.05, standoff 0, extent -14.15,8.35 -13.35,9.15
3D body: height 0.05, standoff 0, extent -12.9,8.35 -12.1,9.15
3D body: height 0.05, standoff 0, extent -12.9,-9.15 -12.1,-8.35
3D body: height 0.05, standoff 0, extent -11.65,-9.15 -10.85,-8.35
3D body: height 0.05, standoff 0, extent -10.4,4.6 -9.6,5.4
3D body: height 0.05, standoff 0, extent -11.65,9.6 -10.85,10.4
3D body: height 0.05, standoff 0, extent -14.15,9.6 -13.35,10.4
3D body: height 0.05, standoff 0, extent -12.9,9.6 -12.1,10.4
3D body: height 0.05, standoff 0, extent -12.9,-7.9 -12.1,-7.1
3D body: height 0.05, standoff 0, extent -11.65,-7.9 -10.85,-7.1
3D body: height 0.05, standoff 0, extent -10.4,5.85 -9.6,6.65
3D body: height 0.05, standoff 0, extent -11.65,10.85 -10.85,11.65
3D body: height 0.05, standoff 0, extent -14.15,10.85 -13.35,11.65
3D body: height 0.05, standoff 0, extent -12.9,10.85 -12.1,11.65
3D body: height 0.05, standoff 0, extent -12.9,-6.65 -12.1,-5.85
3D body: height 0.05, standoff 0, extent -11.65,-6.65 -10.85,-5.85
3D body: height 0.05, standoff 0, extent -10.4,7.1 -9.6,7.9
3D body: height 0.05, standoff 0, extent -11.65,12.1 -10.85,12.9
3D body: height 0.05, standoff 0, extent -14.15,12.1 -13.35,12.9
3D body: height 0.05, standoff 0, extent -12.9,12.1 -12.1,12.9
3D body: height 0.05, standoff 0, extent -12.9,-5.4 -12.1,-4.6
3D body: height 0.05, standoff 0, extent -11.65,-5.4 -10.85,-4.6
3D body: height 0.05, standoff 0, extent -10.4,8.35 -9.6,9.15
3D body: height 0.05, standoff 0, extent -11.65,13.35 -10.85,14.15
3D body: height 0.05, standoff 0, extent -12.9,13.35 -12.1,14.15
3D body: height 0.05, standoff 0, extent -1.65,12.1 -0.85,12.9
3D body: height 0.05, standoff 0, extent -1.65,10.85 -0.85,11.65
3D body: height 0.05, standoff 0, extent -1.65,9.6 -0.85,10.4
3D body: height 0.05, standoff 0, extent -10.4,9.6 -9.6,10.4
3D body: height 0.05, standoff 0, extent -9.15,9.6 -8.35,10.4
3D body: height 0.05, standoff 0, extent -7.9,9.6 -7.1,10.4
3D body: height 0.05, standoff 0, extent -6.65,9.6 -5.85,10.4
3D body: height 0.05, standoff 0, extent -5.4,9.6 -4.6,10.4
3D body: height 0.05, standoff 0, extent -4.15,9.6 -3.35,10.4
3D body: height 0.05, standoff 0, extent -2.9,9.6 -2.1,10.4
3D body: height 0.05, standoff 0, extent -10.4,10.85 -9.6,11.65
3D body: height 0.05, standoff 0, extent -9.15,10.85 -8.35,11.65
3D body: height 0.05, standoff 0, extent -7.9,10.85 -7.1,11.65
3D body: height 0.05, standoff 0, extent -6.65,10.85 -5.85,11.65
3D body: height 0.05, standoff 0, extent -5.4,10.85 -4.6,11.65
3D body: height 0.05, standoff 0, extent -4.15,10.85 -3.35,11.65
3D body: height 0.05, standoff 0, extent -2.9,10.85 -2.1,11.65
3D body: height 0.05, standoff 0, extent -10.4,12.1 -9.6,12.9
3D body: height 0.05, standoff 0, extent -9.15,12.1 -8.35,12.9
3D body: height 0.05, standoff 0, extent -7.9,12.1 -7.1,12.9
3D body: height 0.05, standoff 0, extent -6.65,12.1 -5.85,12.9
3D body: height 0.05, standoff 0, extent -5.4,12.1 -4.6,12.9
3D body: height 0.05, standoff 0, extent -4.15,12.1 -3.35,12.9
3D body: height 0.05, standoff 0, extent -2.9,12.1 -2.1,12.9
3D body: height 0.05, standoff 0, extent -10.4,13.35 -9.6,14.15
3D body: height 0.05, standoff 0, extent -9.15,13.35 -8.35,14.15
3D body: height 0.05, standoff 0, extent -7.9,13.35 -7.1,14.15
3D body: height 0.05, standoff 0, extent -6.65,13.35 -5.85,14.15
3D body: height 0.05, standoff 0, extent -5.4,13.35 -4.6,14.15
3D body: height 0.05, standoff 0, extent -4.15,13.35 -3.35,14.15
3D body: height 0.05, standoff 0, extent -2.9,13.35 -2.1,14.15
